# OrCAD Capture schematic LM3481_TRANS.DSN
size Custom; title: LM3481: High Efficiency Low-Side N-Channel Controller for; rev: 1.0; note: Datasheet :SNVS346E   EVM:SNVA304A
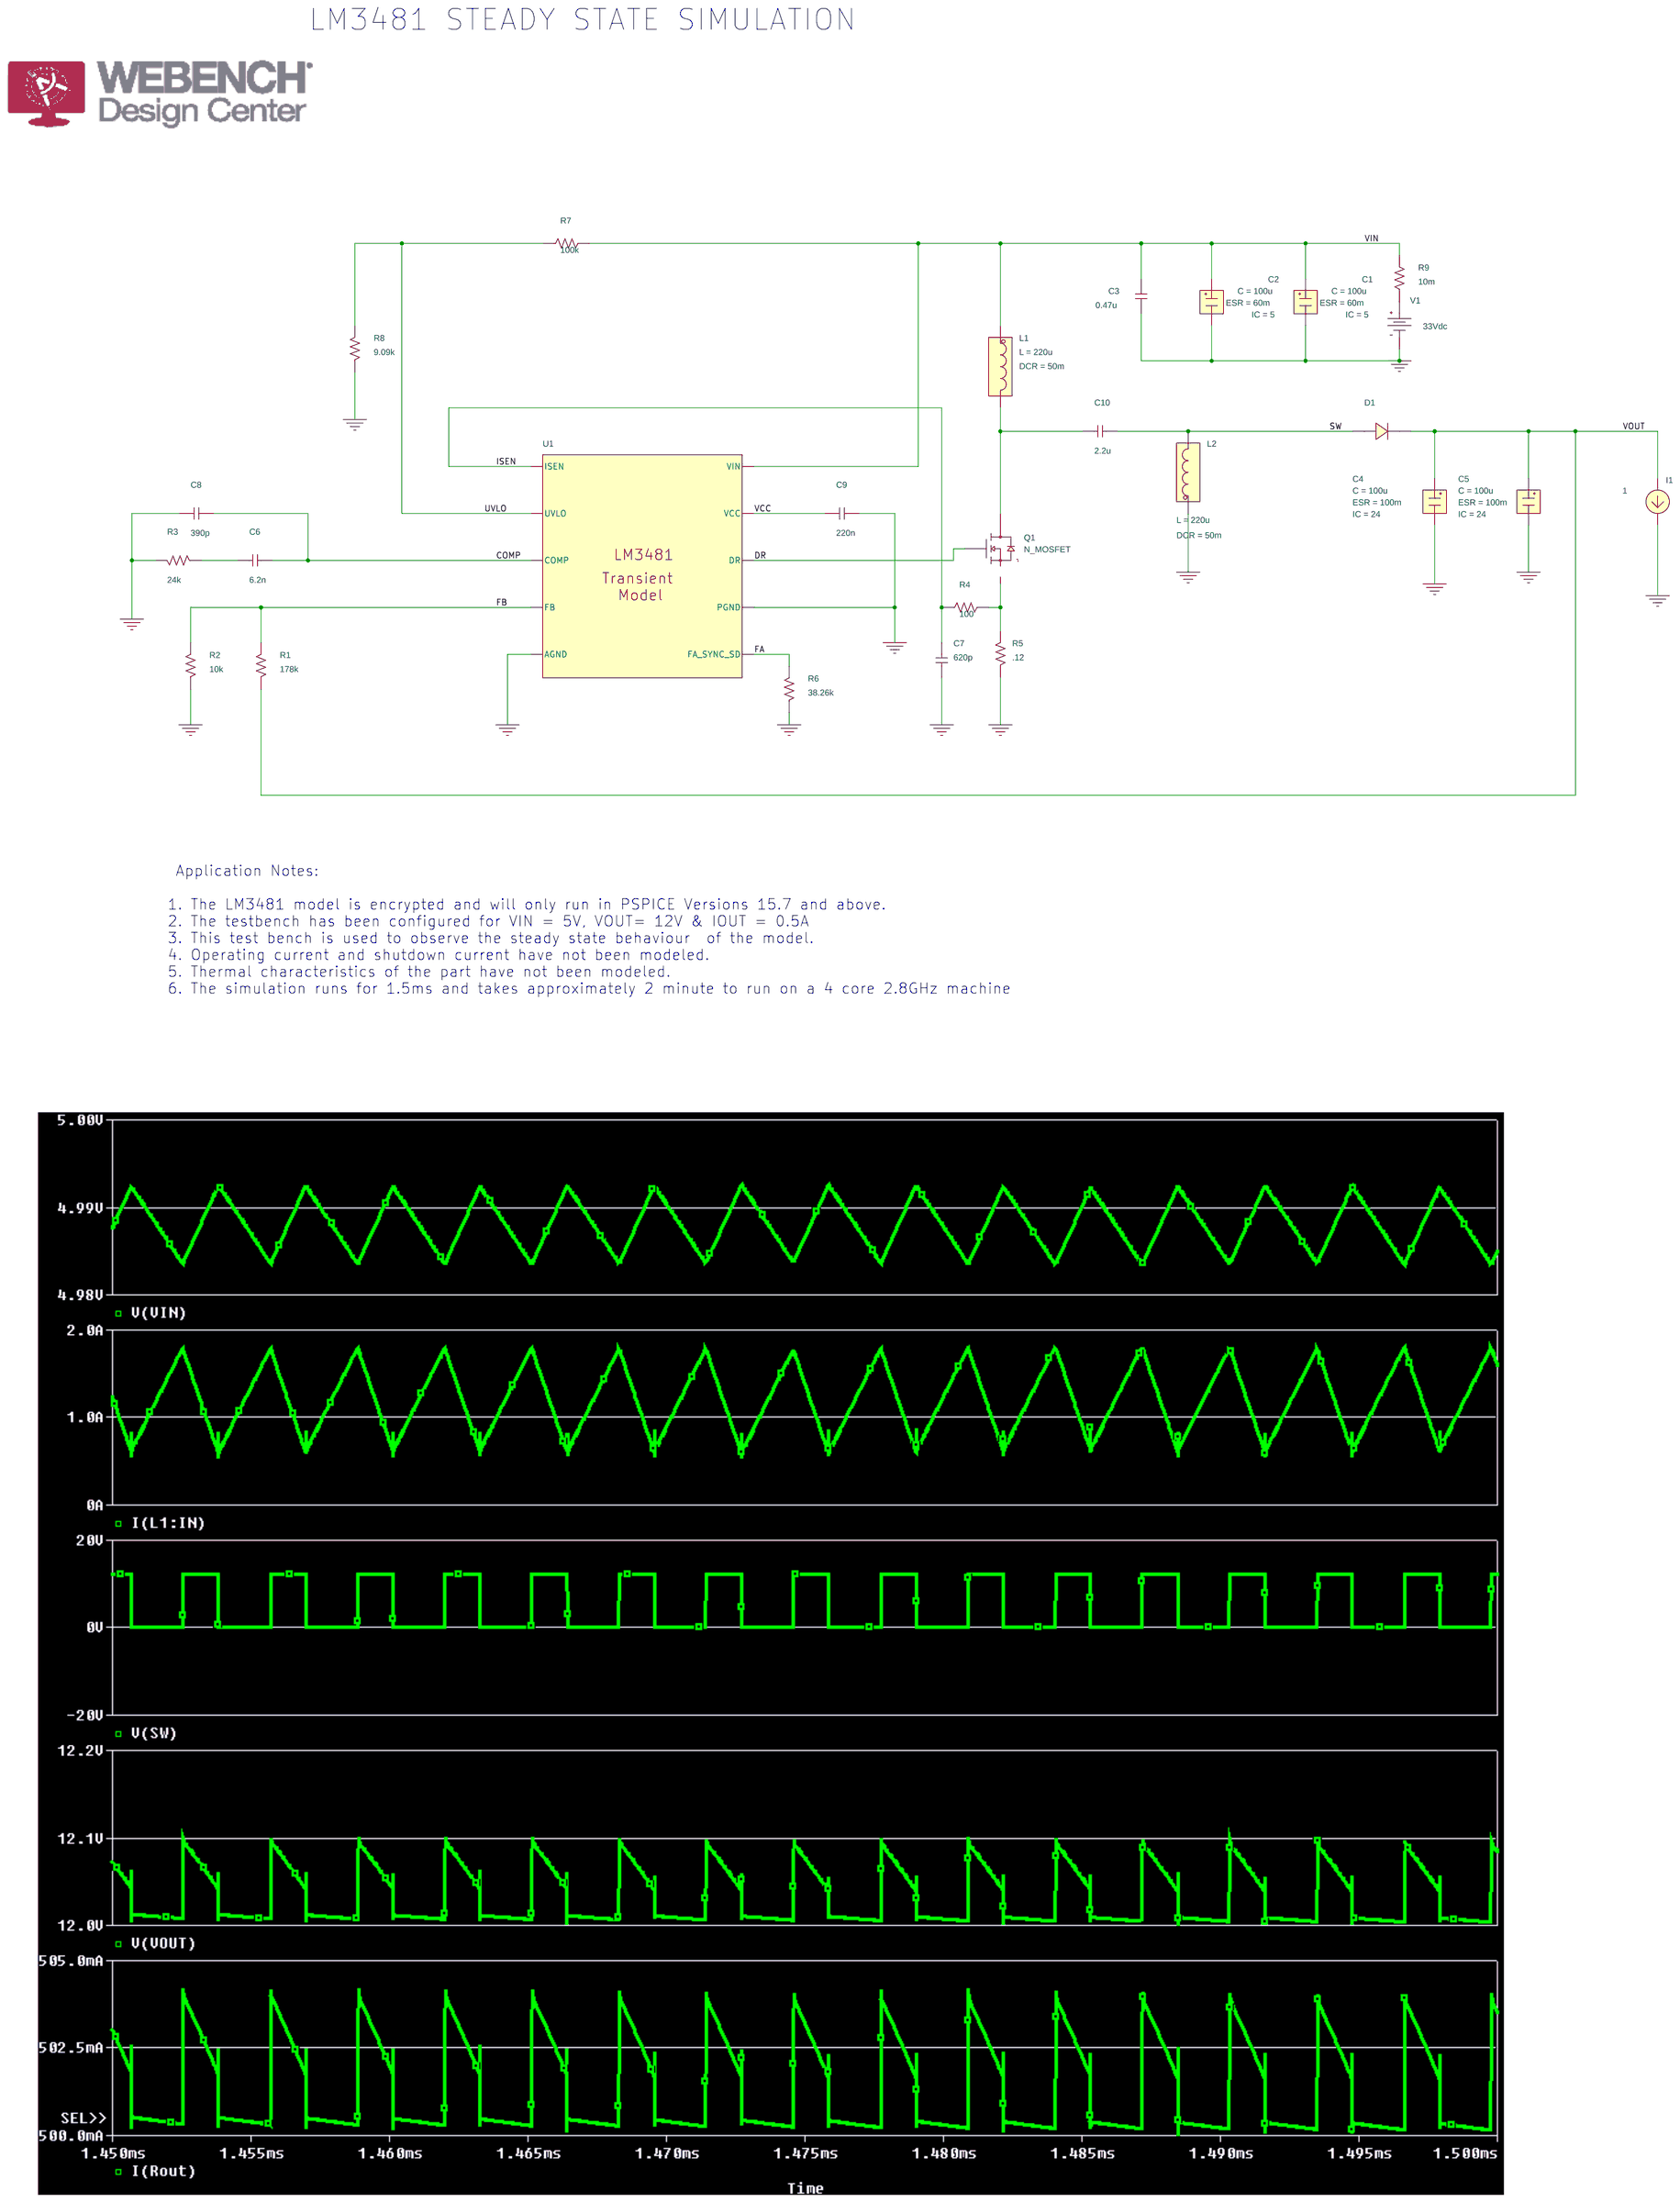
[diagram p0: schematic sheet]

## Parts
C1  CESR
C2  CESR
C3  0.47u  [RAD/CK05]
C4  CESR
C5  CESR
C6  6.2n  [RAD/CK05]
C7  620p  [RAD/CK05]
C8  390p  [RAD/CK05]
C9  220n  [RAD/CK05]
C10  2.2u  [RAD/CK05]
D1  D_D1
I1  IDC
L1  LDCR
L2  LDCR
Q1  N_MOSFET
R1  178k  [AX/RC05]
R2  10k  [AX/RC05]
R3  24k  [AX/RC05]
R4  100  [AX/RC05]
R5  .12  [AX/RC05]
R6  38.26k  [AX/RC05]
R7  100k  [AX/RC05]
R8  9.09k  [AX/RC05]
R9  10m  [AX/RC05]
U1  LM3481_TRANS
V1  VDC

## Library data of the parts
C1 C2 = CESR_8: C: 100u; ESR: 60m; IC: 5; PSpiceTemplate: X^@REFDES %IN %OUT @MODEL PARAMS:  ?C|C=@C||C=100u|  ?ESR|ESR=@ESR||ESR=0.01| ?IC|IC=@IC||IC=2|
C3 C6-C10 = C
C4 C5 = CESR_8: C: 100u; ESR: 100m; IC: 24; PSpiceTemplate: X^@REFDES %IN %OUT @MODEL PARAMS:  ?C|C=@C||C=100u|  ?ESR|ESR=@ESR||ESR=0.01| ?IC|IC=@IC||IC=2|
D1 = D_D1
I1 = IDC: DC: 1
L1 L2 = LDCR_0: DCR: 50m; L: 220u; PSpiceTemplate: X^@REFDES %IN %OUT @MODEL PARAMS:  ?L|L=@L||L=1u|  ?DCR|DCR=@DCR||DCR=0.01|
Q1 = csd17507q5a
R1-R9 = R
U1 = LM3481_TRANS
V1 = VDC: DC: 33Vdc

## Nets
VCC: C9.2 U1.VCC
VIN: C1.1(IN) C2.1(IN) C3.2 L1.1(IN) R7.2 R9.2 U1.VIN
0: C1.3(OUT) C2.3(OUT) C3.1 C4.3(OUT) C5.3(OUT) C7.1 C8.2 C9.1 I1.2(-) L2.1(IN) R2.1 R3.2 R5.1 R6.1 R8.1 U1.AGND U1.PGND V1.1(-)
COMP: C6.1 C8.1 U1.COMP
DR: Q1.gate U1.DR
FA: R6.2 U1.FA_SYNC_SD
FB: R1.2 R2.2 U1.FB
ISEN: C7.2 R4.1 U1.ISEN
SW: C10.1 D1.2(A) L2.3(OUT)
UVLO: R7.1 R8.2 U1.UVLO
VOUT: C4.1(IN) C5.1(IN) D1.1(C) I1.1(+) R1.1
N16769677: Q1.source R4.2 R5.2
N16770452: C10.2 L1.3(OUT) Q1.drain
N16833280: C6.2 R3.1
N16888622: R9.1 V1.0(+)

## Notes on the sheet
- LM3481 STEADY STATE SIMULATION
- Application Notes:
  1. The LM3481 model is encrypted and will only run in PSPICE Versions 15.7 and above.
  2. The testbench has been configured for VIN = 5V, VOUT= 12V & IOUT = 0.5A
  3. This test bench is used to observe the steady state behaviour  of the model.
  4. Operating current and shutdown current have not been modeled.
  5. Thermal characteristics of the part have not been modeled.
  6. The simulation runs for 1.5ms and takes approximately 2 minute to run on a 4 core 2.8GHz machine
